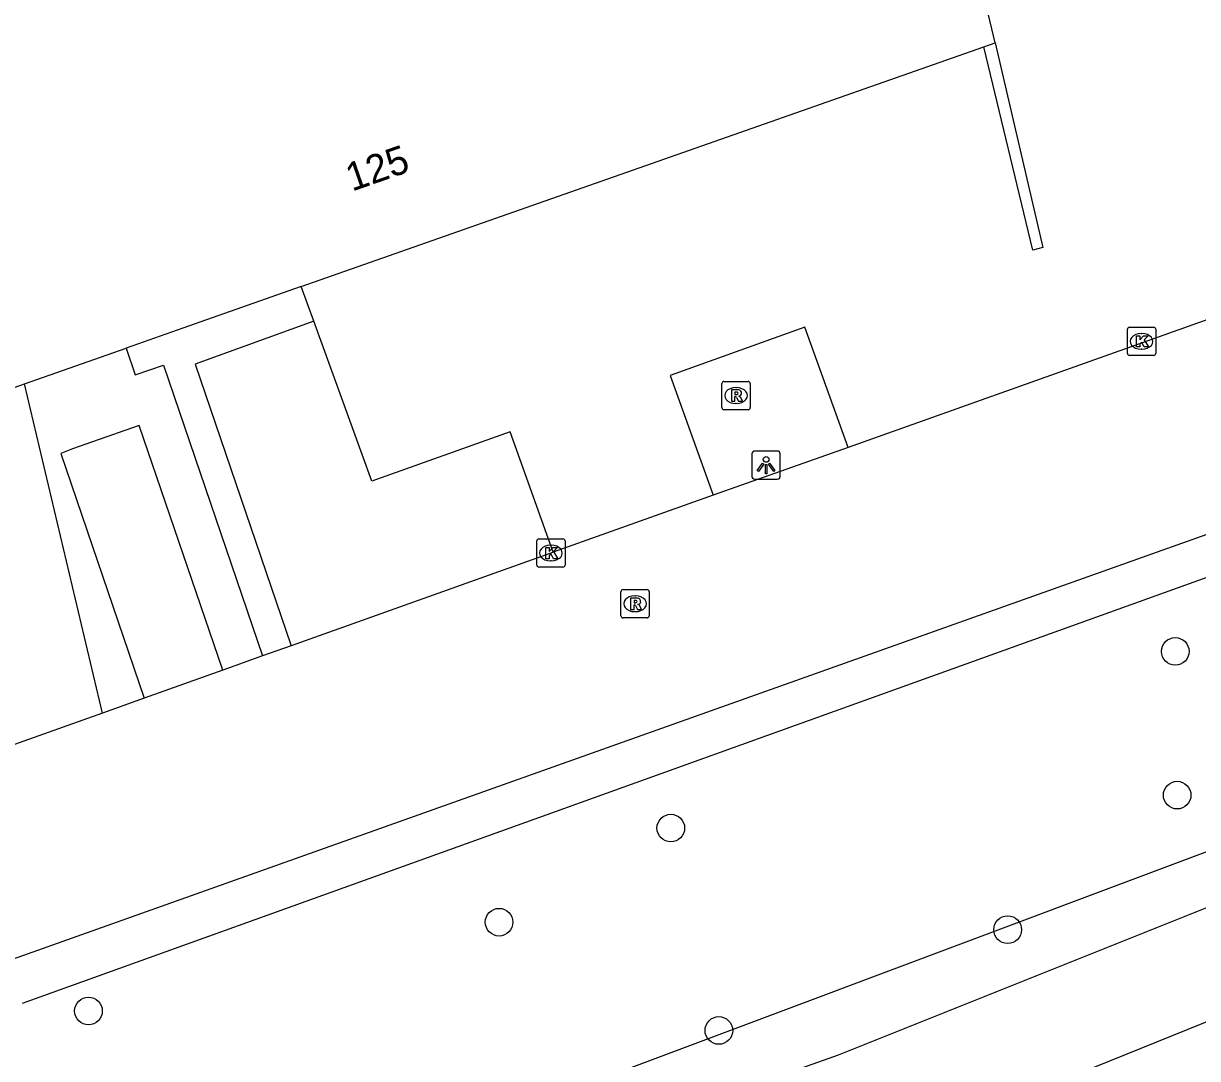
# Model space of a CAD drawing. Extents: x 161389 to 162585, y 388479 to 389761.
# Drawn here: x 162138.42 to 162179.93, y 388516.93 to 388553.53 of the extents above; entities that cross this region are included whole.
import ezdxf

# ---------------------------------------------------------------- set-up
doc = ezdxf.new("R2010")
doc.units = 0
for name, color, linetype in [('IMGEO_Berm_groen', 7, 'Continuous'), ('IMGEO_Boom', 7, 'Continuous'), ('IMGEO_Fietspad_gesloten', 7, 'Continuous'), ('IMGEO_Groenvoorziening', 7, 'Continuous'), ('IMGEO_Kolk', 7, 'Continuous'), ('IMGEO_Lichtpunt', 7, 'Continuous'), ('IMGEO_Muur', 7, 'Continuous'), ('IMGEO_Pand', 7, 'Continuous'), ('IMGEO_Pand_nummerreeks', 7, 'Continuous'), ('IMGEO_Rijbaan_lokaal_gesloten', 7, 'Continuous'), ('IMGEO_Rioolput', 7, 'Continuous'), ('IMGEO_Voetpad_open', 7, 'Continuous')]:
    doc.layers.add(name, color=color, linetype=linetype)

msp = doc.modelspace()

# ---------------------------------------------------------------- linework, layer by layer
at = {"layer": 'IMGEO_Berm_groen'}
for points in [[(162138.38, 388518.892), (162215.574, 388546.64), (162252.986, 388559.158), (162288.362, 388570.488), (162317.268, 388578.974), (162336.532, 388584.978)], [(162338.047, 388580.195), (162324.599, 388576.081), (162287.169, 388563.505), (162279.038, 388561.214), (162264.796, 388556.642), (162259.025, 388554.101), (162254.71, 388552.825), (162240.969, 388547.955), (162222.876, 388540.549), (162201.4, 388532.175), (162133.055, 388506.534)]]:
    msp.add_lwpolyline(points, dxfattribs=at)
at = {"layer": 'IMGEO_Boom'}
for centre in [(162179.146, 388531.324), (162179.214, 388526.243), (162161.31, 388525.078), (162155.237, 388521.751), (162173.222, 388521.486), (162140.718, 388518.61), (162163.009, 388517.923)]:
    msp.add_circle(centre, 0.489, dxfattribs=at)
at = {"layer": 'IMGEO_Fietspad_gesloten'}
for points in [[(162209.962, 388534.05), (162197.575, 388529.185), (162167.231, 388517.05), (162128.073, 388503.157), (162120.579, 388500.721), (162117.419, 388499.693)], [(162164.193, 388511.274), (162164.054, 388511.643), (162165.808, 388512.398), (162201.647, 388526.877), (162205.548, 388528.526)]]:
    msp.add_lwpolyline(points, dxfattribs=at)
at = {"layer": 'IMGEO_Groenvoorziening'}
for points in [[(162157.155, 388534.834), (162155.629, 388539.084), (162150.733, 388537.349), (162148.686, 388543.003)], [(162167.575, 388538.539), (162166.052, 388542.788), (162161.281, 388541.085), (162162.809, 388536.844)]]:
    msp.add_lwpolyline(points, dxfattribs=at)
at = {"layer": 'IMGEO_Kolk'}
for p, q in [((162177.453, 388541.862), (162177.453, 388542.714)), ((162177.528, 388542.788), (162178.38, 388542.788)), ((162177.941, 388542.568), (162177.966, 388542.568)), ((162178.454, 388542.714), (162178.454, 388541.862)), ((162178.38, 388541.788), (162177.528, 388541.788)), ((162177.964, 388542.008), (162177.939, 388542.008)), ((162156.567, 388534.378), (162156.567, 388535.23)), ((162156.642, 388535.304), (162157.494, 388535.304)), ((162157.055, 388535.084), (162157.08, 388535.084)), ((162157.568, 388535.23), (162157.568, 388534.378)), ((162157.494, 388534.304), (162156.642, 388534.304)), ((162157.078, 388534.524), (162157.053, 388534.524))]:
    msp.add_line(p, q, dxfattribs=at)
for points in [[(162177.453, 388541.862), (162177.453, 388542.714)], [(162177.528, 388542.788), (162178.38, 388542.788)], [(162178.454, 388542.714), (162178.454, 388541.862)], [(162177.774, 388542.488), (162177.897, 388542.488), (162177.897, 388542.337), (162178.027, 388542.488), (162178.191, 388542.488), (162178.045, 388542.337), (162178.198, 388542.088), (162178.046, 388542.088), (162177.961, 388542.252), (162177.897, 388542.185), (162177.897, 388542.088), (162177.774, 388542.088), (162177.774, 388542.488)], [(162178.38, 388541.788), (162177.528, 388541.788)], [(162156.567, 388534.378), (162156.567, 388535.23)], [(162156.642, 388535.304), (162157.494, 388535.304)], [(162157.568, 388535.23), (162157.568, 388534.378)], [(162156.888, 388535.004), (162157.011, 388535.004), (162157.011, 388534.853), (162157.141, 388535.004), (162157.305, 388535.004), (162157.159, 388534.853), (162157.312, 388534.604), (162157.16, 388534.604), (162157.075, 388534.768), (162157.011, 388534.701), (162157.011, 388534.604), (162156.888, 388534.604), (162156.888, 388535.004)], [(162157.494, 388534.304), (162156.642, 388534.304)]]:
    msp.add_lwpolyline(points, dxfattribs=at)
for centre, start, end in [((162177.53, 388542.712), 91.552, 178.448), ((162177.53, 388542.712), 91.552, 178.448), ((162178.378, 388542.712), 1.552, 88.448), ((162178.378, 388542.712), 1.552, 88.448), ((162177.53, 388541.864), 181.552, 268.448), ((162177.53, 388541.864), 181.552, 268.448), ((162178.378, 388541.864), 271.552, 358.448), ((162178.378, 388541.864), 271.552, 358.448), ((162156.644, 388535.228), 91.552, 178.448), ((162156.644, 388535.228), 91.552, 178.448), ((162157.492, 388535.228), 1.552, 88.448), ((162157.492, 388535.228), 1.552, 88.448), ((162156.644, 388534.38), 181.552, 268.448), ((162156.644, 388534.38), 181.552, 268.448), ((162157.492, 388534.38), 271.552, 358.448), ((162157.492, 388534.38), 271.552, 358.448)]:
    msp.add_arc(centre, 0.0765, start, end, dxfattribs=at)
for centre, major_axis, ratio, start_param, end_param in [((162177.94, 388542.288), (-0.387, 0.002), 0.722429, 4.712389, 7.853982), ((162177.965, 388542.288), (-0.39, 0.002), 0.717154, 1.570796, 4.712389), ((162157.054, 388534.804), (-0.387, 0.002), 0.722429, 4.712389, 7.853982), ((162157.079, 388534.804), (-0.39, 0.002), 0.717154, 1.570796, 4.712389)]:
    msp.add_ellipse(centre, major_axis=major_axis, ratio=ratio, start_param=start_param, end_param=end_param, dxfattribs=at)
at = {"layer": 'IMGEO_Lichtpunt'}
for p, q in [((162165.082, 388538.41), (162164.274, 388538.41)), ((162165.082, 388538.41), (162164.274, 388538.41)), ((162164.18, 388538.315), (162164.18, 388537.508)), ((162164.18, 388538.315), (162164.18, 388537.508)), ((162165.176, 388537.508), (162165.176, 388538.315)), ((162165.176, 388537.508), (162165.176, 388538.315)), ((162164.274, 388537.414), (162165.082, 388537.414)), ((162164.274, 388537.414), (162165.082, 388537.414))]:
    msp.add_line(p, q, dxfattribs=at)
for points in [[(162164.554, 388537.979), (162164.593, 388537.951), (162164.405, 388537.689), (162164.367, 388537.716), (162164.554, 388537.979)], [(162164.766, 388537.951), (162164.804, 388537.978), (162164.991, 388537.716), (162164.952, 388537.688), (162164.766, 388537.951)], [(162164.656, 388537.931), (162164.703, 388537.931), (162164.703, 388537.609), (162164.656, 388537.609), (162164.656, 388537.931)]]:
    msp.add_lwpolyline(points, dxfattribs=at)
msp.add_circle((162164.679, 388538.113), 0.0994, dxfattribs=at)
for centre, start, end in [((162164.274, 388538.315), 90, 180), ((162164.274, 388538.315), 90, 180), ((162165.082, 388538.315), 0, 90), ((162165.082, 388538.315), 0, 90), ((162164.274, 388537.508), 180, 270), ((162164.274, 388537.508), 180, 270), ((162165.082, 388537.508), 270, 0), ((162165.082, 388537.508), 270, 360)]:
    msp.add_arc(centre, 0.0946, start, end, dxfattribs=at)
at = {"layer": 'IMGEO_Muur'}
msp.add_lwpolyline([(162172.773, 388552.843), (162174.465, 388545.605), (162174.113, 388545.508), (162172.374, 388552.698)], dxfattribs=at)
at = {"layer": 'IMGEO_Pand'}
for points in [[(162172.773, 388552.843), (162167.708, 388574.1), (162179.646, 388577.025), (162166.514, 388614.639), (162117.232, 388599.583)], [(162148.243, 388544.225), (162172.374, 388552.698)], [(162172.374, 388552.698), (162172.773, 388552.843)], [(162148.243, 388544.225), (162144.059, 388542.756), (162142.05, 388542.051)], [(162138.46, 388540.79), (162142.05, 388542.051)], [(162133.381, 388531.67), (162132.074, 388537.422), (162131.778, 388538.547), (162135.47, 388539.74), (162138.46, 388540.79)]]:
    msp.add_lwpolyline(points, dxfattribs=at)
at = {"layer": 'IMGEO_Rijbaan_lokaal_gesloten'}
for points in [[(162316.848, 388580.491), (162315.105, 388579.927), (162225.932, 388551.675), (162217.932, 388548.854), (162137.852, 388520.378)], [(162196.492, 388548.826), (162178.209, 388542.32), (162167.575, 388538.539)], [(162167.575, 388538.539), (162162.809, 388536.844)], [(162162.809, 388536.844), (162157.155, 388534.834)], [(162157.155, 388534.834), (162157.068, 388534.803), (162147.884, 388531.527)], [(162147.884, 388531.527), (162146.877, 388531.168)], [(162146.877, 388531.168), (162145.47, 388530.665)], [(162145.47, 388530.665), (162142.688, 388529.673)], [(162142.688, 388529.673), (162141.211, 388529.146)], [(162141.211, 388529.146), (162137.028, 388527.654), (162135.877, 388527.269)]]:
    msp.add_lwpolyline(points, dxfattribs=at)
at = {"layer": 'IMGEO_Rioolput'}
for p, q in [((162163.19, 388540.871), (162164.042, 388540.871)), ((162163.115, 388539.945), (162163.115, 388540.797)), ((162163.603, 388540.651), (162163.628, 388540.651)), ((162164.116, 388540.797), (162164.116, 388539.945)), ((162163.626, 388540.091), (162163.601, 388540.091)), ((162164.042, 388539.871), (162163.19, 388539.871)), ((162159.547, 388532.584), (162159.547, 388533.436)), ((162159.622, 388533.51), (162160.474, 388533.51)), ((162160.548, 388533.436), (162160.548, 388532.584)), ((162160.035, 388533.29), (162160.06, 388533.29)), ((162160.058, 388532.73), (162160.033, 388532.73)), ((162160.474, 388532.51), (162159.622, 388532.51))]:
    msp.add_line(p, q, dxfattribs=at)
for points in [[(162163.19, 388540.871), (162164.042, 388540.871)], [(162163.115, 388539.945), (162163.115, 388540.797)], [(162163.704, 388540.569), (162163.452, 388540.571), (162163.452, 388540.171)], [(162163.63, 388540.49), (162163.576, 388540.49), (162163.576, 388540.409)], [(162164.116, 388540.797), (162164.116, 388539.945)], [(162163.452, 388540.171), (162163.576, 388540.171), (162163.576, 388540.333), (162163.587, 388540.333)], [(162163.576, 388540.409), (162163.628, 388540.409)], [(162163.634, 388540.304), (162163.705, 388540.171), (162163.845, 388540.171), (162163.78, 388540.297)], [(162164.042, 388539.871), (162163.19, 388539.871)], [(162159.547, 388532.584), (162159.547, 388533.436)], [(162159.622, 388533.51), (162160.474, 388533.51)], [(162160.548, 388533.436), (162160.548, 388532.584)], [(162160.136, 388533.208), (162159.884, 388533.21), (162159.884, 388532.81)], [(162160.062, 388533.129), (162160.008, 388533.129), (162160.008, 388533.048)], [(162160.008, 388533.048), (162160.06, 388533.048)], [(162159.884, 388532.81), (162160.008, 388532.81), (162160.008, 388532.972), (162160.019, 388532.972)], [(162160.066, 388532.943), (162160.137, 388532.81), (162160.277, 388532.81), (162160.212, 388532.936)], [(162160.474, 388532.51), (162159.622, 388532.51)]]:
    msp.add_lwpolyline(points, dxfattribs=at)
for centre, radius, start, end in [((162163.192, 388540.795), 0.0765, 91.552, 178.448), ((162163.192, 388540.795), 0.0765, 91.552, 178.448), ((162164.04, 388540.795), 0.0765, 1.552, 88.448), ((162164.04, 388540.795), 0.0765, 1.552, 88.448), ((162163.636, 388540.394), 0.0964, 77.0061, 93.1865), ((162163.65, 388540.451), 0.0378, 276.6634, 79.6772), ((162163.703, 388540.459), 0.109, 350.3612, 89.416), ((162163.586, 388540.28), 0.0533, 26.0293, 88.6989), ((162163.612, 388540.598), 0.19, 274.7715, 282.9687), ((162163.701, 388540.459), 0.112, 277.5842, 350.9817), ((162163.685, 388540.244), 0.108, 29.5134, 73.7905), ((162163.192, 388539.947), 0.0765, 181.552, 268.448), ((162163.192, 388539.947), 0.0765, 181.552, 268.448), ((162164.04, 388539.947), 0.0765, 271.552, 358.448), ((162164.04, 388539.947), 0.0765, 271.552, 358.448), ((162159.624, 388533.434), 0.0765, 91.552, 178.448), ((162159.624, 388533.434), 0.0765, 91.552, 178.448), ((162160.472, 388533.434), 0.0765, 1.552, 88.448), ((162160.472, 388533.434), 0.0765, 1.552, 88.448), ((162160.044, 388533.237), 0.19, 274.7715, 282.9687), ((162160.068, 388533.033), 0.0964, 77.0061, 93.1865), ((162160.082, 388533.09), 0.0378, 276.6634, 79.6772), ((162160.135, 388533.098), 0.109, 350.3612, 89.416), ((162160.133, 388533.098), 0.112, 277.5842, 350.9817), ((162160.117, 388532.883), 0.108, 29.5134, 73.7905), ((162159.624, 388532.586), 0.0765, 181.552, 268.448), ((162159.624, 388532.586), 0.0765, 181.552, 268.448), ((162160.018, 388532.919), 0.0533, 26.0293, 88.6989), ((162160.472, 388532.586), 0.0765, 271.552, 358.448), ((162160.472, 388532.586), 0.0765, 271.552, 358.448)]:
    msp.add_arc(centre, radius, start, end, dxfattribs=at)
for centre, major_axis, ratio, start_param, end_param in [((162163.602, 388540.371), (-0.387, 0.002), 0.722429, 4.712389, 7.853982), ((162163.627, 388540.371), (-0.39, 0.002), 0.717154, 1.570796, 4.712389), ((162160.034, 388533.01), (-0.387, 0.002), 0.722429, 4.712389, 7.853982), ((162160.059, 388533.01), (-0.39, 0.002), 0.717154, 1.570796, 4.712389)]:
    msp.add_ellipse(centre, major_axis=major_axis, ratio=ratio, start_param=start_param, end_param=end_param, dxfattribs=at)
at = {"layer": 'IMGEO_Voetpad_open'}
for points in [[(162148.686, 388543.003), (162148.243, 388544.225)], [(162148.686, 388543.003), (162144.492, 388541.484), (162147.884, 388531.527)], [(162142.05, 388542.051), (162142.365, 388541.103), (162143.375, 388541.449), (162146.877, 388531.168)], [(162141.211, 388529.146), (162138.46, 388540.79)], [(162145.47, 388530.665), (162142.515, 388539.31), (162140.151, 388538.486), (162139.742, 388538.317), (162142.688, 388529.673)]]:
    msp.add_lwpolyline(points, dxfattribs=at)

# ---------------------------------------------------------------- texts
at = {"layer": 'IMGEO_Pand_nummerreeks'}
msp.add_text('125', height=1, rotation=19.2169, dxfattribs=at).set_placement((162150.034, 388547.579))

doc.saveas('drawing.dxf')
